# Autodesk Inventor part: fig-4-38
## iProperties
Created: 2004-05
Part Number: fig-4-38
Document SubType Name: Modeling
Designer: CADCIM Technologies
Manufacturer: Standard
Standards Organization: Custom
Density: 1 g/cm^3
Author: CADCIM Technologies
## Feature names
1. Extrusion1
2. Shell1
3. Extrusion2
4. Extrusion7
